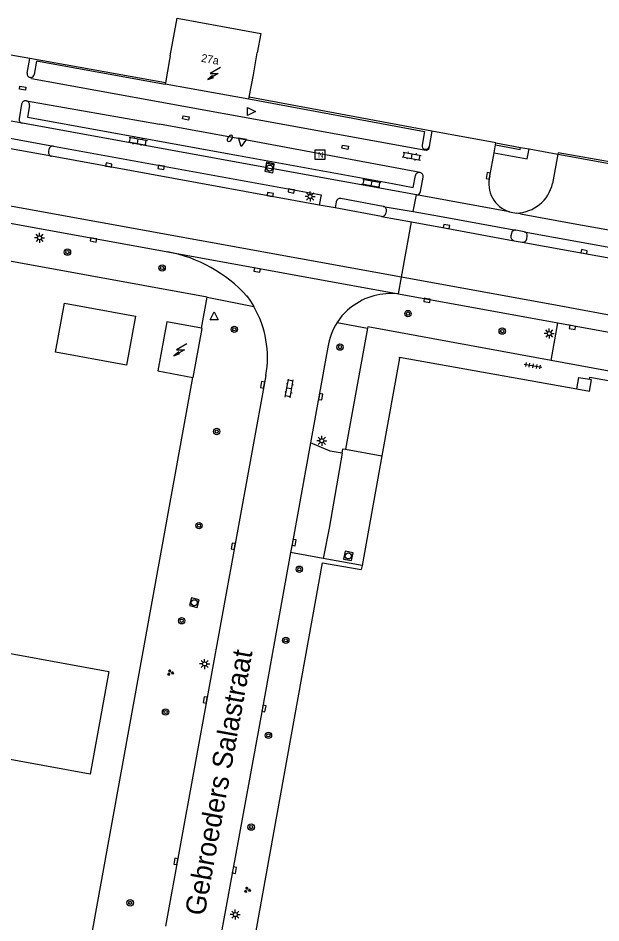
# Model space of a CAD drawing. Extents: x 130998 to 133001, y 398999 to 403002.
# Drawn here: x 131727.9 to 131800.7, y 399593.8 to 399706.9 of the extents above; entities that cross this region are included whole.
import ezdxf

# ---------------------------------------------------------------- set-up
doc = ezdxf.new("R2010")
doc.units = 0
for name, color, linetype in [('gg-afsc-hekwerk', 7, 'Continuous'), ('gg-anno-huisnummerreeks BGT', 7, 'Continuous'), ('gg-anno-openbare ruimte label', 7, 'Continuous'), ('gg-bbg-bijgebouw', 7, 'Continuous'), ('gg-bbg-gedigitaliseerde bijgebouw', 7, 'Continuous'), ('gg-bbg-hoofdgebouw', 7, 'Continuous'), ('gg-bbg-onder overbouw', 7, 'Continuous'), ('gg-bbg-pand overbouw', 7, 'Continuous'), ('gg-knt-verharding', 7, 'Continuous'), ('gg-knt-verharding nz', 7, 'Continuous'), ('gt-grn-groengrens', 7, 'Continuous'), ('gt-grn-weggrens', 7, 'Continuous'), ('gt-symb-boom', 7, 'Continuous'), ('gt-symb-brandkraan', 7, 'Continuous'), ('gt-symb-groenvak', 7, 'Continuous'), ('gt-symb-klinker verharding', 7, 'Continuous'), ('gt-symb-kolk', 7, 'Continuous'), ('gt-symb-kolk center center', 7, 'Continuous'), ('gt-symb-lichtmast', 7, 'Continuous'), ('gt-symb-nortonput', 7, 'Continuous'), ('gt-symb-rioolschacht', 7, 'Continuous'), ('gt-symb-tegel verharding', 7, 'Continuous'), ('gt-symb-trafo symbool', 7, 'Continuous'), ('gt-symb-waterafsluiter', 7, 'Continuous')]:
    doc.layers.add(name, color=color, linetype=linetype)

# ---------------------------------------------------------------- blocks, each defined once
blk = doc.blocks.new('gt0-KOLK')
at = {"layer": 'gt-symb-kolk'}
blk.add_lwpolyline([(0, 0), (0.37, 0), (0.37, 0.4), (-0.38, 0.4), (-0.38, 0), (0, 0)], dxfattribs=at)
blk = doc.blocks.new('gt0-HSP')
at = {"layer": 'gt-symb-trafo symbool'}
for points in [[(0.77, 0.75), (-0.53, 0), (0.47, 0), (-0.83, -0.75)], [(-0.22, -0.24), (-0.83, -0.75), (-0.08, -0.48)]]:
    blk.add_lwpolyline(points, dxfattribs=at)
blk = doc.blocks.new('gt0-KOLKCC')
at = {"layer": 'gt-symb-kolk center center'}
blk.add_lwpolyline([(-0.38, 0.2), (0.38, 0.2), (0.38, -0.2), (-0.38, -0.2)], close=True, dxfattribs=at)
blk = doc.blocks.new('gt0-WAFSL')
at = {"layer": 'gt-symb-waterafsluiter'}
for p, q in [((-0.5, -0.33), (0, 0.67)), ((0, 0.67), (0.5, -0.33)), ((0.5, -0.33), (-0.5, -0.33))]:
    blk.add_line(p, q, dxfattribs=at)
blk = doc.blocks.new('gt0-BR')
at = {"layer": 'gt-symb-brandkraan'}
for centre, radius, start, end in [((-0.24, 0), 0.206, 107.5669, 252.4331), ((0.6, -2.66), 3, 106.892, 107.5669), ((0, -0.69), 0.938, 73.108, 106.892), ((-0.6, -2.66), 3, 72.4331, 73.108), ((0.24, 0), 0.206, 287.567, 72.4331), ((0.6, 2.66), 3, 252.4331, 253.108), ((0, 0.69), 0.938, 253.108, 286.8921), ((-0.6, 2.66), 3, 286.8921, 287.567)]:
    blk.add_arc(centre, radius, start, end, dxfattribs=at)
blk = doc.blocks.new('gt0-KL1')
at = {"layer": 'gt-symb-klinker verharding'}
for p, q in [((-1.15, 0.3), (1.15, 0.3)), ((-1, -0.3), (-1, 0.3)), ((-0.5, 0.3), (-0.5, 0.45)), ((0, -0.3), (0, 0.3)), ((0.5, 0.3), (0.5, 0.45)), ((1, -0.3), (1, 0.3)), ((-1.15, -0.3), (1.15, -0.3)), ((-0.5, -0.45), (-0.5, -0.3)), ((0.5, -0.45), (0.5, -0.3))]:
    blk.add_line(p, q, dxfattribs=at)
blk = doc.blocks.new('gt0-RS')
at = {"layer": 'gt-symb-rioolschacht'}
blk.add_lwpolyline([(-0.5, -0.5), (0.5, -0.5), (0.5, 0.5), (-0.5, 0.5)], close=True, dxfattribs=at)
blk.add_circle((0, 0), 0.375, dxfattribs=at)
blk = doc.blocks.new('gt0-NPUT')
at = {"layer": 'gt-symb-nortonput'}
blk.add_lwpolyline([(-0.57, -0.61), (-0.57, 0.59), (0.63, 0.59), (0.63, -0.61)], close=True, dxfattribs=at)
blk.add_text('N', height=0.7, dxfattribs=at).set_placement((-0.22, -0.38))
blk = doc.blocks.new('gt0-LMAST')
at = {"layer": 'gt-symb-lichtmast'}
for p, q in [((-0.18, 0.17), (-0.45, 0.44)), ((-0.01, 0.25), (-0.01, 0.62)), ((0.17, 0.17), (0.44, 0.44)), ((-0.26, 0), (-0.63, 0)), ((-0.18, -0.18), (-0.45, -0.45)), ((-0.01, -0.25), (-0.01, -0.63)), ((0.44, -0.45), (0.17, -0.18)), ((0.24, 0), (0.62, 0))]:
    blk.add_line(p, q, dxfattribs=at)
blk.add_circle((-0.01, 0), 0.25, dxfattribs=at)
blk = doc.blocks.new('gt0-BOOM')
at = {"layer": 'gt-symb-boom'}
for radius in [0.4, 0.2]:
    blk.add_circle((0, 0), radius, dxfattribs=at)
blk = doc.blocks.new('gt0-TEG1')
at = {"layer": 'gt-symb-tegel verharding'}
for p, q in [((-1.12, 0), (1.12, 0)), ((-0.9, -0.25), (-0.9, 0.25)), ((-0.45, -0.25), (-0.45, 0.25)), ((0, -0.25), (0, 0.25)), ((0.45, -0.25), (0.45, 0.25)), ((0.9, -0.25), (0.9, 0.25))]:
    blk.add_line(p, q, dxfattribs=at)
blk = doc.blocks.new('gt0-GRVAK')
at = {"layer": 'gt-symb-groenvak'}
for p, q in [((-0.11, 0.19), (-0.23, 0.24)), ((-0.18, 0.15), (0.09, 0.15)), ((-0.09, 0.21), (-0.16, 0.32)), ((-0.05, 0.21), (-0.05, 0.39)), ((0, 0.21), (0.06, 0.32)), ((0.01, 0.19), (0.13, 0.24)), ((0.26, -0.05), (0.2, 0.06)), ((0.3, -0.05), (0.3, 0.13)), ((0.35, -0.05), (0.41, 0.06)), ((-0.24, -0.23), (-0.36, -0.18)), ((-0.32, -0.26), (-0.05, -0.26)), ((-0.23, -0.21), (-0.29, -0.09)), ((-0.18, -0.2), (-0.18, -0.02)), ((-0.14, -0.21), (-0.07, -0.09)), ((-0.12, -0.23), (0, -0.18)), ((0.24, -0.07), (0.12, -0.02)), ((0.17, -0.11), (0.44, -0.11)), ((0.37, -0.07), (0.49, -0.02))]:
    blk.add_line(p, q, dxfattribs=at)

msp = doc.modelspace()

# ---------------------------------------------------------------- linework, layer by layer
at = {"layer": 'gg-afsc-hekwerk'}
for p, q in [((131729.36, 399701.8), (131723.69, 399702.82)), ((131746.31, 399698.78), (131729.36, 399701.8)), ((131779.61, 399692.73), (131756.79, 399696.96)), ((131787.58, 399691.25), (131779.61, 399692.73)), ((131787.58, 399691.25), (131790.67, 399690.69)), ((131790.67, 399690.69), (131791.74, 399690.5)), ((131791.74, 399690.5), (131795.34, 399689.85)), ((131795.34, 399689.85), (131802.44, 399688.54)), ((131750.83, 399668.09), (131751.54, 399671.97)), ((131736.74, 399590.33), (131749.73, 399661.96))]:
    msp.add_line(p, q, dxfattribs=at)
msp.add_lwpolyline([(131751.54, 399671.97), (131610.33, 399697.73), (131610.23, 399697.19)], dxfattribs=at)
at = {"layer": 'gg-bbg-bijgebouw'}
msp.add_line((131739.24, 399625.2), (131736.9, 399612.4), dxfattribs=at)
for points in [[(131732.57, 399665.09), (131733.7, 399671.23), (131742.56, 399669.61), (131741.43, 399663.47), (131732.57, 399665.09)], [(131750.83, 399668.09), (131746.5, 399668.89), (131745.38, 399662.76), (131749.73, 399661.96)], [(131749.73, 399661.96), (131749.79, 399661.95), (131750.91, 399668.08), (131750.83, 399668.09)]]:
    msp.add_lwpolyline(points, dxfattribs=at)
at = {"layer": 'gg-bbg-gedigitaliseerde bijgebouw'}
msp.add_lwpolyline([(131736.9, 399612.4), (131706.85, 399617.89), (131709.19, 399630.69), (131739.24, 399625.2)], dxfattribs=at)
at = {"layer": 'gg-bbg-hoofdgebouw'}
for p, q in [((131746.84, 399701.68), (131746.31, 399698.78)), ((131746.92, 399702.14), (131746.84, 399701.68)), ((131757.3, 399699.77), (131757.79, 399702.5)), ((131756.79, 399696.96), (131757.3, 399699.77)), ((131746.31, 399698.78), (131746.29, 399698.65)), ((131746.29, 399698.65), (131756.75, 399696.76)), ((131756.75, 399696.76), (131756.79, 399696.96)), ((131775.54, 399664.34), (131773.34, 399652.15)), ((131773.34, 399652.15), (131770.87, 399638.44)), ((131770.87, 399638.44), (131770.78, 399637.95))]:
    msp.add_line(p, q, dxfattribs=at)
for points in [[(131746.92, 399702.14), (131747.77, 399706.85), (131758.23, 399704.93), (131757.79, 399702.5)], [(131775.54, 399664.34), (131775.57, 399664.48), (131797.71, 399660.53)], [(131799.31, 399661.72), (131799.35, 399662), (131807.47, 399660.52), (131807.41, 399660.23)], [(131757.2, 399590.25), (131765.93, 399638.8), (131770.78, 399637.95)]]:
    msp.add_lwpolyline(points, dxfattribs=at)
at = {"layer": 'gg-bbg-onder overbouw'}
msp.add_lwpolyline([(131797.71, 399660.53), (131799.28, 399660.25), (131799.54, 399661.67), (131799.31, 399661.72)], dxfattribs=at)
at = {"layer": 'gg-bbg-pand overbouw'}
msp.add_lwpolyline([(131797.71, 399660.53), (131797.97, 399661.96), (131799.31, 399661.72)], dxfattribs=at)
at = {"layer": 'gg-knt-verharding'}
for p, q in [((131729.03, 399699.96), (131729.36, 399701.8)), ((131619, 399700.87), (131746.6, 399677.64)), ((131728.34, 399696.09), (131728.05, 399694.27)), ((131728.96, 399696.52), (131728.91, 399696.53)), ((131729.34, 399695.95), (131729.1, 399694.48)), ((131728.44, 399693.71), (131722.14, 399694.86)), ((131758.82, 399688.19), (131728.44, 399693.71)), ((131729.1, 399694.48), (131755.46, 399689.68)), ((131722.56, 399692.62), (131732.32, 399690.85)), ((131779.61, 399692.73), (131779.24, 399690.81)), ((131732.08, 399689.58), (131722.33, 399691.36)), ((131731.76, 399690.43), (131731.71, 399690.17)), ((131787.36, 399690.03), (131787.53, 399691.01)), ((131787.53, 399691.01), (131787.58, 399691.25)), ((131765.53, 399683.49), (131732.08, 399689.58)), ((131755.46, 399689.68), (131774.69, 399686.18)), ((131786.83, 399687.11), (131787.36, 399690.03)), ((131795.34, 399689.85), (131794.67, 399686.18)), ((131777.66, 399684.76), (131759.78, 399688.02)), ((131778.17, 399685.17), (131778.51, 399686.98)), ((131789.28, 399682.65), (131777.66, 399684.76)), ((131767.51, 399683.13), (131765.53, 399683.49)), ((131767.64, 399683.9), (131767.51, 399683.13)), ((131773.53, 399683.33), (131768.22, 399684.32)), ((131773.29, 399682.08), (131767.51, 399683.13)), ((131773.53, 399683.33), (131777.28, 399682.68)), ((131773.87, 399682.47), (131773.92, 399682.72)), ((131790.67, 399682.39), (131790.18, 399682.48)), ((131790.67, 399682.39), (131797.23, 399681.2)), ((131773.29, 399682.08), (131777.05, 399681.4)), ((131797.23, 399681.2), (131805.66, 399679.67)), ((131791.14, 399680.16), (131790.09, 399680.35)), ((131791.14, 399680.16), (131807.26, 399677.21)), ((131789.53, 399679.95), (131789.46, 399679.66)), ((131789.88, 399679.04), (131790.86, 399678.85)), ((131791.45, 399679.26), (131791.51, 399679.59)), ((131790.86, 399678.85), (131807.02, 399675.95)), ((131746.6, 399677.64), (131775.41, 399672.4)), ((131775.41, 399672.4), (131795.34, 399668.77)), ((131795.34, 399668.77), (131809.42, 399666.2)), ((131771.54, 399668.09), (131768.82, 399652.97)), ((131766.62, 399665.72), (131764.44, 399653.79)), ((131808.56, 399661.46), (131794.5, 399664.06)), ((131758.86, 399662.2), (131746.33, 399593.38)), ((131768.82, 399652.97), (131773.34, 399652.15)), ((131766.03, 399639.32), (131761.93, 399640.07)), ((131770.87, 399638.44), (131766.03, 399639.32))]:
    msp.add_line(p, q, dxfattribs=at)
for points in [[(131746.29, 399698.65), (131746.27, 399698.56), (131730.19, 399701.46), (131729.92, 399699.81)], [(131756.75, 399696.76), (131778.69, 399692.68), (131778.37, 399690.96)], [(131732.32, 399690.85), (131765.75, 399684.78), (131765.53, 399683.49)], [(131787.36, 399690.03), (131791.51, 399689.25), (131791.74, 399690.5)], [(131787.53, 399691.01), (131790.62, 399690.44), (131790.67, 399690.69)], [(131802.44, 399688.54), (131802.48, 399688.75), (131795.37, 399690.02), (131795.34, 399689.85)], [(131759.78, 399688.02), (131759.88, 399688.66), (131758.95, 399688.83), (131758.82, 399688.19)], [(131774.69, 399686.18), (131777.26, 399685.69), (131777.54, 399687.17)], [(131777.28, 399682.68), (131780.55, 399682.11), (131790.09, 399680.35)], [(131777.05, 399681.4), (131781.39, 399680.61), (131789.88, 399679.04)], [(131756.48, 399672.13), (131756.94, 399671.49), (131757.35, 399670.82)], [(131794.5, 399664.06), (131771.58, 399668.29), (131771.54, 399668.09)], [(131768.38, 399652.47), (131766.89, 399652.75), (131764.44, 399653.79)], [(131768.38, 399652.47), (131768.49, 399653.03), (131768.82, 399652.97)], [(131761.93, 399640.07), (131758.42, 399620.61), (131753.08, 399591.33)]]:
    msp.add_lwpolyline(points, dxfattribs=at)
for centre, radius, start, end in [((131729.47, 399699.89), 0.446, 171.1685, 274.6664), ((131729.48, 399699.89), 0.445, 274.5038, 350.3112), ((131728.84, 399696.03), 0.504, 82.5476, 173.1743), ((131728.84, 399696.03), 0.507, 350.6717, 76.2001), ((131728.55, 399694.2), 0.507, 173.112, 257.0796), ((131732.25, 399690.36), 0.497, 81.5222, 171.3364), ((131778.81, 399690.88), 0.444, 170.269, 256.1124), ((131778.79, 399690.91), 0.463, 259.2902, 347.7459), ((131732.17, 399690.05), 0.472, 165.2991, 259.2226), ((131778.03, 399687.08), 0.496, 79.7497, 169.806), ((131778, 399687.06), 0.52, 350.4538, 77.0154), ((131790.39, 399686.16), 3.68, 164.9371, 252.5476), ((131790.07, 399687.2), 4.71, 271.3482, 347.5646), ((131777.7, 399685.23), 0.47, 265.5319, 351.9823), ((131768.15, 399683.81), 0.516, 82.0556, 170.0227), ((131773.37, 399682.58), 0.507, 260.5873, 347.7029), ((131773.43, 399682.84), 0.498, 346.7511, 79.1697), ((131790.39, 399686.2), 3.72, 252.6608, 266.7407), ((131790.02, 399679.86), 0.492, 81.822, 169.116), ((131791.04, 399679.69), 0.48, 348.2512, 78.0023), ((131790, 399679.57), 0.541, 170.0051, 257.9673), ((131790.93, 399679.37), 0.529, 262.7561, 347.4782), ((131743.29, 399660.1), 17.85, 42.3605, 79.302), ((131774.51, 399664.31), 8.13, 83.6417, 127.4712), ((131746.37, 399664.45), 12.69, 349.8022, 30.1196), ((131774.28, 399664.64), 7.74, 127.5834, 147.1603), ((131774.28, 399664.64), 7.74, 147.2058, 172.009)]:
    msp.add_arc(centre, radius, start, end, dxfattribs=at)
at = {"layer": 'gg-knt-verharding nz'}
for p, q in [((131775.79, 399674.47), (131619.73, 399702.87)), ((131728.96, 399696.52), (131745.58, 399693.61)), ((131755.83, 399691.71), (131745.58, 399693.61)), ((131778.12, 399687.57), (131755.83, 399691.71)), ((131795.72, 399670.84), (131775.79, 399674.47)), ((132000, 399633.66), (131795.72, 399670.84))]:
    msp.add_line(p, q, dxfattribs=at)
for points in [[(131779.24, 399690.81), (131779.18, 399690.45), (131778.94, 399690.32), (131778.63, 399690.36), (131729.58, 399699.25), (131729.51, 399699.44)], [(131764.44, 399653.79), (131762.18, 399641.34), (131761.93, 399640.07)]]:
    msp.add_lwpolyline(points, dxfattribs=at)
at = {"layer": 'gt-grn-groengrens'}
for p, q in [((131751.54, 399671.97), (131757.35, 399670.82)), ((131767.78, 399668.83), (131771.54, 399668.09)), ((131794.5, 399664.06), (131795.34, 399668.77))]:
    msp.add_line(p, q, dxfattribs=at)
at = {"layer": 'gt-grn-weggrens'}
for p, q in [((131758.82, 399688.19), (131759.78, 399688.02)), ((131777.28, 399682.68), (131777.66, 399684.76)), ((131775.79, 399674.47), (131777.05, 399681.4)), ((131775.41, 399672.4), (131775.79, 399674.47))]:
    msp.add_line(p, q, dxfattribs=at)
msp.add_lwpolyline([(131768.38, 399652.47), (131766.76, 399643.12), (131766.03, 399639.32)], dxfattribs=at)

# ---------------------------------------------------------------- block references
at = {"layer": 'gt-symb-boom'}
for p in [(131734.07, 399677.61), (131745.9, 399675.62), (131776.61, 399669.93), (131754.92, 399667.96), (131788.39, 399667.74), (131768.12, 399665.74), (131752.72, 399655.2), (131750.51, 399643.43), (131763.04, 399637.99), (131748.34, 399631.55), (131761.35, 399629.1), (131746.33, 399620.15), (131759.18, 399617.24), (131757.02, 399605.77), (131741.91, 399596.31)]:
    msp.add_blockref('gt0-BOOM', p, dxfattribs=at)
at = {"layer": 'gt-symb-brandkraan', "rotation": -126.5834211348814}
msp.add_blockref('gt0-BR', (131754.37, 399691.82), dxfattribs=at)
at = {"layer": 'gt-symb-groenvak'}
for p in [(131746.92, 399625.07), (131756.54, 399597.92)]:
    msp.add_blockref('gt0-GRVAK', p, dxfattribs=at)
at = {"layer": 'gt-symb-klinker verharding'}
for p, rotation in [((131742.87, 399691.47), -9.96151659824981), ((131777.09, 399689.6), -10.30997039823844), ((131772.03, 399686.2), 169.5669752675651), ((131761.79, 399660.57), 79.69002960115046)]:
    msp.add_blockref('gt0-KL1', p, dxfattribs=dict(at, rotation=rotation))
at = {"layer": 'gt-symb-kolk'}
for p, rotation in [((131739.2, 399688.29), -10.366322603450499), ((131745.81, 399688.4), 169.69002960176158), ((131786.83, 399687.11), 79.7615574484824), ((131759.38, 399684.61), -10.25359802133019), ((131762.07, 399685.45), 169.63367739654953), ((131781.39, 399680.61), -10.467966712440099), ((131737.35, 399679.33), 169.69002960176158), ((131798.58, 399677.46), -10.189360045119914), ((131757.8, 399675.56), 169.57734546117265), ((131779.02, 399671.78), 171.0839632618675), ((131797.18, 399668.4), 169.4542656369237), ((131758.65, 399660.99), 79.92566727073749), ((131765.51, 399659.58), -100.30997039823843), ((131762.18, 399641.34), -100.25359802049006), ((131754.97, 399640.82), 79.6336773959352), ((131751.47, 399621.63), 79.6900296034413), ((131758.42, 399620.61), -100.25359802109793), ((131747.81, 399601.45), 79.69002960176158), ((131754.73, 399600.42), -100.36632260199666)]:
    msp.add_blockref('gt0-KOLK', p, dxfattribs=dict(at, rotation=rotation))
at = {"layer": 'gt-symb-kolk center center'}
for p, rotation in [((131728.48, 399698.1), -10.30997039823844), ((131748.85, 399694.38), -10.30997039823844), ((131768.76, 399690.71), -10.309970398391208)]:
    msp.add_blockref('gt0-KOLKCC', p, dxfattribs=dict(at, rotation=rotation))
at = {"layer": 'gt-symb-lichtmast'}
for p in [(131764.4, 399684.56), (131730.6, 399679.4), (131794.27, 399667.44), (131765.86, 399654.04), (131751.22, 399626.15), (131755.05, 399594.84)]:
    msp.add_blockref('gt0-LMAST', p, dxfattribs=at)
at = {"layer": 'gt-symb-nortonput'}
msp.add_blockref('gt0-NPUT', (131765.6, 399689.78), dxfattribs=at)
at = {"layer": 'gt-symb-rioolschacht'}
for p, rotation in [((131759.32, 399688.11), -100.65836150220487), ((131769.16, 399639.65), 78.99333582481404), ((131749.92, 399633.81), -104.5365092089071)]:
    msp.add_blockref('gt0-RS', p, dxfattribs=dict(at, rotation=rotation))
at = {"layer": 'gt-symb-tegel verharding', "rotation": -9.905079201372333}
msp.add_blockref('gt0-TEG1', (131792.25, 399663.41), dxfattribs=at)
at = {"layer": 'gt-symb-trafo symbool'}
for p in [(131752.42, 399699.92), (131748.21, 399665.41)]:
    msp.add_blockref('gt0-HSP', p, dxfattribs=at)
at = {"layer": 'gt-symb-waterafsluiter'}
for p, rotation in [((131756.88, 399695.2), -90.00000000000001), ((131755.89, 399691.48), 169.74640197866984)]:
    msp.add_blockref('gt0-WAFSL', p, dxfattribs=dict(at, rotation=rotation))
msp.add_blockref('gt0-WAFSL', (131752.39, 399669.47), dxfattribs=at)

# ---------------------------------------------------------------- texts
at = {"layer": 'gg-anno-huisnummerreeks BGT'}
msp.add_text('27a', height=1, rotation=349.7, dxfattribs=at).set_placement((131750.71, 399701.41))
at = {"layer": 'gg-anno-openbare ruimte label'}
msp.add_text('Gebroeders Salastraat', height=2.5, rotation=79.7, dxfattribs=at).set_placement((131751.19, 399594.59))

doc.saveas('drawing.dxf')
